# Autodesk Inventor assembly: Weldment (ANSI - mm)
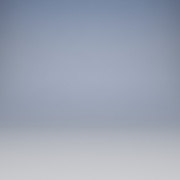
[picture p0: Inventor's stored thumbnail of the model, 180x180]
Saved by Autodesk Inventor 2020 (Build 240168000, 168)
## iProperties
Length Units: 11269
Angle Units: 11283
Time Units: 11279
Mass Units: 11290
Length Display Precision: 3
Angle Display Precision: 2
Part Number: Weldment (ANSI - mm)
Document SubType Name: Weldment
Created: 2002-06
Designer: smithga
Created: 2002-08
Weld Material: Welded Aluminum-6061
Manager: www.cadconsulting.pl
Company: Fabian Stasiak CAD Consulting
Control State: 0
Master: False
Shininess: 64.0
Angle Units: 11279
Time Units: 11290
Mass Units: 11283
Compacted: True
Density: 0.0
Volumn: 0.0
Area: 0.0
PropertySet Name: Model Information
Author: F.Stasiak
Subject: Zbiór ćwiczeń. Autodesk Inventor 2020. Kurs podstawowy
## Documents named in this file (1)
- M:\AUTOBUILD\M24_168_RTM\Application\App\Templates\en-US\Metric\Weldment (ANSI - mm).iam
